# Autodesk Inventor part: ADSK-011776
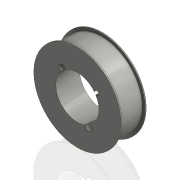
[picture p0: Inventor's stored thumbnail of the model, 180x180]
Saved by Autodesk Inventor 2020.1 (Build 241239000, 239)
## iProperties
Created: 1999-11
Part Number: ADSK-011776
Description: SPRKT,TIMING,8MM X 48T,2012 BUSH
Document SubType Name: Modeling
Designer: mpflueger
Material: Générique
Density: 1 g/cm^3
Appearance: Steel
Mass: 309.139 g
Surface Area: 468.826 cm^2
Volume: 309.139 cm^3
Control State: 0
Checked Out: False
Last Check In By: cmcgourin
Last Check In Date: 1999-12-06
Master: False
Shininess: 0.0
Length Units: 11269
Angle Units: 11279
Time Units: 11290
Mass Units: 11283
Length Display Precision: 3
Angle Display Precision: 2
Compacted: True
Dimensions: 131x38x131 mm
Mass: 0,309 kg
DocNumber: ADSK-011776.ipt
Folder: 01 - Themengebiete\Simplification\01 - Packaging machine\
VDS_Category: 3D Komponenten
VLT_Material: Generic
Density: 0.0
Volumn: 0.0
Area: 0.0
PropertySet Name: Model Information
Author: mpflueger
Revision Number: -
Title: wheel
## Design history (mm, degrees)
node "Solide1"
  node "Extrusion1" dims "d0" = 38, "d1" = 0
  node "Extrusion3" dims "d8" = 1.5, "d9" = 0
  node "Extrusion4" dims "d10" = 1.5, "d11" = 0
sketch "Sketch1"
  geometry: C1 r 35 at (0, 0); C2 r 61 at (0, 0)
  constraints: 2 centre point, 1 coincident
  dimensions: "d2" = 70 diameter of C1; "d3" = 122 diameter of C2
sketch "Sketch3"
  geometry: C1 r 61 at (0, 0) reference; C2 r 65.5 at (0, 0)
  constraints: 1 centre point, 1 coincident
  dimensions: "d7" = 131 diameter of C2
sketch "Skizze7"
  geometry: L1 (0, 0)-(35, 0); L2 (22.498, 26.812)-(0, 0); L3 (0, 0)-(-17.5, -30.311); L4 (0, 0)-(-28.67, 20.075); A1 r 35 centre (0, 0) between (22.498, 26.812) and (35, 0); 1 further point
  constraints: 8 end point, 4 point on circle, 1 centre point, 1 coincident, 1 horizontal
  dimensions: "d17" = 70 diameter of A1; "d19" = 50 deg angle of L2 L1; "d20" = 120 deg angle of L1 L3; "d28" = 95 deg angle of L4 L3
hole "Bohrung2" sketch "Skizze7" at (-28.67, 20.075) diameter "d29" = 6.6; stored, may be unused: countersink angle "d33" = 90 deg, drill point angle "d35" = 118 deg; dims "d30" = 6, "d31" = 4, "d32" = 2, "d34" = 8
workplane "Arbeitsebene1"
sketch "Sketch4"
  geometry: C1 r 61 at (0, 0) reference; C2 r 65.5 at (0, 0) reference
feature "Flächenverjüngung1" dims angle "d16" = 4 deg
hole "Bohrung1" sketch "Skizze7" diameter "d21" = 10; stored, may be unused: countersink angle "d25" = 90 deg, drill point angle "d27" = 118 deg; dims "d22" = 6, "d23" = 4, "d24" = 2, "d26" = 8
node "Corps solides"
node "Corps surfaciques"
